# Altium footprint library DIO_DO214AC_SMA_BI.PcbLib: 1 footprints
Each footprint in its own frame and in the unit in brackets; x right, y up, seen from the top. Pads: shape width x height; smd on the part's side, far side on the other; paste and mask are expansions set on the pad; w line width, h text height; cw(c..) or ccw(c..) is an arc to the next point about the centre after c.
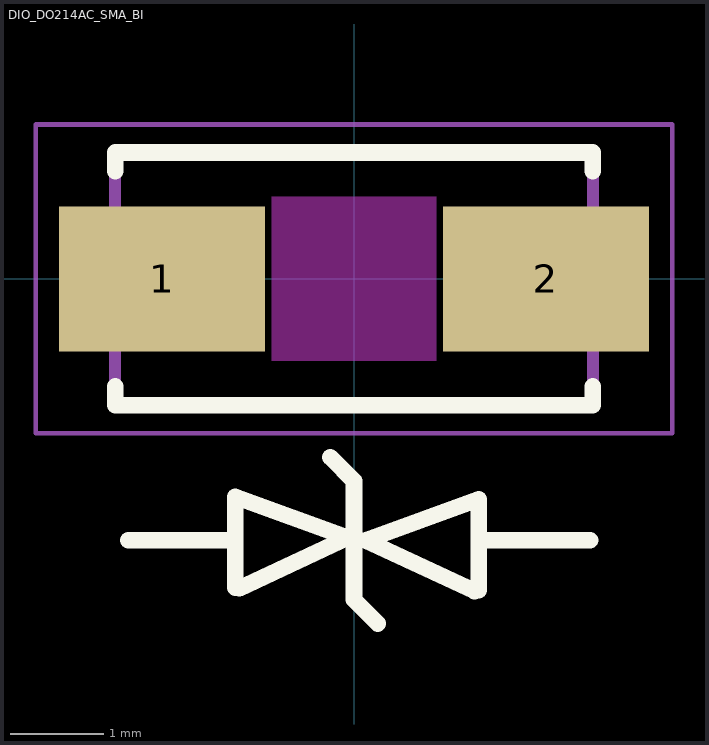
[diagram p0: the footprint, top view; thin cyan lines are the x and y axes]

## DIO_DO214AC_SMA_BI [mm] "DIODE, BIDIRECTIONAL, DO-214AC, 2-PIN"
height 2.29
pads (2):
  rect 2.2x1.55 smd: 1(-2.05,0) 2(2.05,0)
Top Overlay:
  lines w0.178: -2.55,-1.15 -2.55,-1.35 2.55,-1.35 2.55,-1.15 ; -2.55,1.15 -2.55,1.35 2.55,1.35 2.55,1.15 ; -2.413,-2.794 -1.288,-2.794 ; -1.27,-3.298 -1.27,-2.326 -0.064,-2.765 -1.226,-3.307 -1.27,-3.29 ; -0.254,-1.905 0,-2.159 0,-3.429 0.254,-3.683 ; 1.288,-3.336 0.127,-2.794 1.333,-2.356 1.333,-3.327 ; 1.397,-2.794 2.522,-2.794
  text ".Designator" at -1.015,1.937 h1.02
Keep-Out Layer:
  rectangle: -0.88,-0.88 0.88,0.88
Mechanical 5:
  lines w0.127: -2.413,-2.794 -1.288,-2.794 ; -1.27,-3.298 -1.27,-2.326 -0.064,-2.765 -1.226,-3.307 ; -0.254,-1.905 0,-2.159 0,-3.429 0.254,-3.683 ; 1.288,-3.336 0.127,-2.794 1.333,-2.356 1.333,-3.327 ; 1.397,-2.794 2.522,-2.794 ; -2.552,-1.332 -2.552,1.332 ; -2.552,-1.332 -2.552,1.332 ; -2.552,-1.332 2.552,-1.332 2.552,1.332 -2.552,1.332
  text ".Designator" at -1.524,-0.508 h1.02
Mechanical 15:
  lines w0.05: -3.4,-1.65 -3.4,1.65 3.4,1.65 3.4,-1.65 -3.4,-1.65
Mechanical 17:
  text "FOOTPRINT FOR BI-DIRECTIONAL USE ONLY" at -7,-0.029 h0.5
3D body: height 2.29, standoff 0, extent -2.552,-1.332 2.552,1.332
